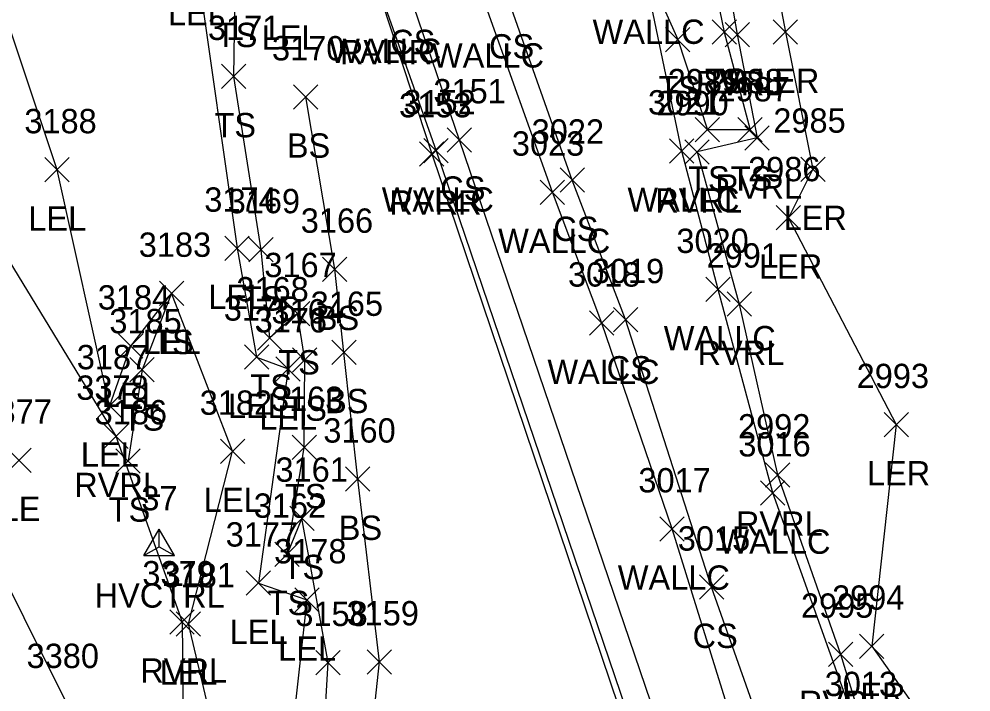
# Model space of a CAD drawing. Extents: x 1461855 to 1464118, y 556196 to 557441.
# Drawn here: x 1462111.2 to 1462189.5, y 556558.7 to 556614 of the extents above; entities that cross this region are included whole.
import ezdxf

# ---------------------------------------------------------------- set-up
doc = ezdxf.new("R2010")
doc.units = 0
for name, color, linetype in [('C_A', 7, 'Continuous'), ('C_I', 7, 'Continuous'), ('CPSM', 7, 'Continuous'), ('L_A', 7, 'Continuous'), ('L_I', 7, 'Continuous'), ('L_TIC', 7, 'Continuous'), ('LARO', 7, 'Continuous'), ('LAWE', 7, 'Continuous'), ('LELB', 7, 'Continuous'), ('LW', 7, 'Continuous')]:
    doc.layers.add(name, color=color, linetype=linetype)

msp = doc.modelspace()

# ---------------------------------------------------------------- linework, layer by layer
at = {"layer": 'CPSM'}
for p, q in [((1462121.477, 556569.921), (1462122.727, 556572.087)), ((1462123.977, 556569.921), (1462122.727, 556572.087)), ((1462122.727, 556570.643), (1462122.727, 556572.087)), ((1462121.477, 556569.921), (1462122.727, 556570.643)), ((1462122.727, 556570.643), (1462122.727, 556570.643)), ((1462122.727, 556570.643), (1462123.977, 556569.921)), ((1462121.477, 556569.921), (1462123.977, 556569.921))]:
    msp.add_line(p, q, dxfattribs=at)
at = {"layer": 'L_TIC'}
for points in [[(1462168.186, 556611.955), (1462170.186, 556613.955)], [(1462170.186, 556611.955), (1462168.186, 556613.955)], [(1462169.255, 556611.748), (1462171.255, 556613.748)], [(1462171.255, 556611.748), (1462169.255, 556613.748)], [(1462173.213, 556611.956), (1462175.213, 556613.956)], [(1462175.213, 556611.956), (1462173.213, 556613.956)], [(1462164.363, 556611.34), (1462166.363, 556613.34)], [(1462166.363, 556611.34), (1462164.363, 556613.34)], [(1462127.864, 556608.306), (1462129.864, 556610.306)], [(1462129.864, 556608.306), (1462127.864, 556610.306)], [(1462133.783, 556606.627), (1462135.783, 556608.627)], [(1462135.783, 556606.627), (1462133.783, 556608.627)], [(1462166.802, 556603.927), (1462168.802, 556605.927)], [(1462168.802, 556603.927), (1462166.802, 556605.927)], [(1462166.802, 556603.927), (1462168.802, 556605.927)], [(1462168.802, 556603.927), (1462166.802, 556605.927)], [(1462170.305, 556603.927), (1462172.305, 556605.927)], [(1462172.305, 556603.927), (1462170.305, 556605.927)], [(1462146.397, 556603.094), (1462148.397, 556605.094)], [(1462148.397, 556603.094), (1462146.397, 556605.094)], [(1462170.886, 556603.258), (1462172.886, 556605.258)], [(1462172.886, 556603.258), (1462170.886, 556605.258)], [(1462144.141, 556601.946), (1462146.141, 556603.946)], [(1462146.141, 556601.946), (1462144.141, 556603.946)], [(1462144.491, 556602.196), (1462146.491, 556604.196)], [(1462146.491, 556602.196), (1462144.491, 556604.196)], [(1462164.687, 556602.179), (1462166.687, 556604.179)], [(1462166.687, 556602.179), (1462164.687, 556604.179)], [(1462165.942, 556602.106), (1462167.942, 556604.106)], [(1462167.942, 556602.106), (1462165.942, 556604.106)], [(1462113.339, 556600.636), (1462115.339, 556602.636)], [(1462115.339, 556600.636), (1462113.339, 556602.636)], [(1462175.476, 556600.682), (1462177.476, 556602.682)], [(1462177.476, 556600.682), (1462175.476, 556602.682)], [(1462155.686, 556599.782), (1462157.686, 556601.782)], [(1462157.686, 556599.782), (1462155.686, 556601.782)], [(1462154.06, 556598.794), (1462156.06, 556600.794)], [(1462156.06, 556598.794), (1462154.06, 556600.794)], [(1462173.457, 556596.693), (1462175.457, 556598.693)], [(1462175.457, 556596.693), (1462173.457, 556598.693)], [(1462128.13, 556594.188), (1462130.13, 556596.188)], [(1462130.13, 556594.188), (1462128.13, 556596.188)], [(1462130.108, 556594.062), (1462132.108, 556596.062)], [(1462132.108, 556594.062), (1462130.108, 556596.062)], [(1462136.166, 556592.458), (1462138.166, 556594.458)], [(1462138.166, 556592.458), (1462136.166, 556594.458)], [(1462167.671, 556590.797), (1462169.671, 556592.797)], [(1462169.671, 556590.797), (1462167.671, 556592.797)], [(1462122.746, 556590.48), (1462124.746, 556592.48)], [(1462124.746, 556590.48), (1462122.746, 556592.48)], [(1462122.746, 556590.48), (1462124.746, 556592.48)], [(1462124.746, 556590.48), (1462122.746, 556592.48)], [(1462169.42, 556589.593), (1462171.42, 556591.593)], [(1462171.42, 556589.593), (1462169.42, 556591.593)], [(1462133.114, 556588.81), (1462135.114, 556590.81)], [(1462135.114, 556588.81), (1462133.114, 556590.81)], [(1462160.076, 556588.318), (1462162.076, 556590.318)], [(1462162.076, 556588.318), (1462160.076, 556590.318)], [(1462158.111, 556588.032), (1462160.111, 556590.032)], [(1462160.111, 556588.032), (1462158.111, 556590.032)], [(1462130.816, 556586.817), (1462132.816, 556588.817)], [(1462132.816, 556586.817), (1462130.816, 556588.817)], [(1462119.375, 556586.146), (1462121.375, 556588.146)], [(1462121.375, 556586.146), (1462119.375, 556588.146)], [(1462129.737, 556585.238), (1462131.737, 556587.238)], [(1462131.737, 556585.238), (1462129.737, 556587.238)], [(1462136.922, 556585.627), (1462138.922, 556587.627)], [(1462138.922, 556585.627), (1462136.922, 556587.627)], [(1462133.696, 556585.005), (1462135.696, 556587.005)], [(1462135.696, 556585.005), (1462133.696, 556587.005)], [(1462120.325, 556584.195), (1462122.325, 556586.195)], [(1462122.325, 556584.195), (1462120.325, 556586.195)], [(1462132.324, 556584.263), (1462134.324, 556586.263)], [(1462134.324, 556584.263), (1462132.324, 556586.263)], [(1462117.651, 556581.24), (1462119.651, 556583.24)], [(1462119.651, 556581.24), (1462117.651, 556583.24)], [(1462182.325, 556579.689), (1462184.325, 556581.689)], [(1462184.325, 556579.689), (1462182.325, 556581.689)], [(1462118.177, 556578.727), (1462120.177, 556580.727)], [(1462120.177, 556578.727), (1462118.177, 556580.727)], [(1462127.758, 556577.494), (1462129.758, 556579.494)], [(1462129.758, 556577.494), (1462127.758, 556579.494)], [(1462133.658, 556577.811), (1462135.658, 556579.811)], [(1462135.658, 556577.811), (1462133.658, 556579.811)], [(1462110.215, 556576.756), (1462112.215, 556578.756)], [(1462112.215, 556576.756), (1462110.215, 556578.756)], [(1462119.172, 556576.711), (1462121.172, 556578.711)], [(1462121.172, 556576.711), (1462119.172, 556578.711)], [(1462138.049, 556575.21), (1462140.049, 556577.21)], [(1462140.049, 556575.21), (1462138.049, 556577.21)], [(1462172.572, 556575.55), (1462174.572, 556577.55)], [(1462174.572, 556575.55), (1462172.572, 556577.55)], [(1462172.165, 556574.068), (1462174.165, 556576.068)], [(1462174.165, 556574.068), (1462172.165, 556576.068)], [(1462133.464, 556571.989), (1462135.464, 556573.989)], [(1462135.464, 556571.989), (1462133.464, 556573.989)], [(1462163.895, 556571.115), (1462165.895, 556573.115)], [(1462165.895, 556571.115), (1462163.895, 556573.115)], [(1462132.244, 556569.031), (1462134.244, 556571.031)], [(1462134.244, 556569.031), (1462132.244, 556571.031)], [(1462129.889, 556566.664), (1462131.889, 556568.664)], [(1462131.889, 556566.664), (1462129.889, 556568.664)], [(1462167.136, 556566.331), (1462169.136, 556568.331)], [(1462169.136, 556566.331), (1462167.136, 556568.331)], [(1462133.873, 556565.28), (1462135.873, 556567.28)], [(1462135.873, 556565.28), (1462133.873, 556567.28)], [(1462123.613, 556563.474), (1462125.613, 556565.474)], [(1462125.613, 556563.474), (1462123.613, 556565.474)], [(1462124.133, 556563.305), (1462126.133, 556565.305)], [(1462126.133, 556563.305), (1462124.133, 556565.305)], [(1462177.747, 556560.813), (1462179.747, 556562.813)], [(1462179.747, 556560.813), (1462177.747, 556562.813)], [(1462180.304, 556561.472), (1462182.304, 556563.472)], [(1462182.304, 556561.472), (1462180.304, 556563.472)], [(1462135.613, 556560.13), (1462137.613, 556562.13)], [(1462137.613, 556560.13), (1462135.613, 556562.13)], [(1462139.834, 556560.185), (1462141.834, 556562.185)], [(1462141.834, 556560.185), (1462139.834, 556562.185)]]:
    msp.add_lwpolyline(points, dxfattribs=at)
at = {"layer": 'LARO'}
for points in [[(1462153.543, 556698.226), (1462159.529, 556693.305), (1462162.233, 556679.751), (1462167.682, 556662.613), (1462169.082, 556643.16), (1462171.862, 556625.321), (1462174.213, 556612.956), (1462176.476, 556601.682), (1462174.457, 556597.693), (1462183.325, 556580.689), (1462181.304, 556562.472), (1462189.463, 556550.975), (1462182.605, 556534.635)], [(1462128.267, 556551.138), (1462125.133, 556564.305), (1462128.758, 556578.494), (1462123.746, 556591.48), (1462120.375, 556587.146), (1462118.651, 556582.24), (1462114.339, 556601.636), (1462108.703, 556618.463), (1462098.448, 556617.236), (1462094.693, 556608.84), (1462088.622, 556617.99), (1462090.264, 556635.589), (1462093.761, 556646.388), (1462094.044, 556655.088), (1462088.409, 556655.405), (1462085.382, 556651.508), (1462082.004, 556651.265), (1462078.128, 556651.639), (1462079.126, 556665.539), (1462072.726, 556676.797)], [(1462108.44, 556677.046), (1462114.001, 556662.205), (1462116.197, 556655.209), (1462120.026, 556641.487), (1462125.669, 556630.824), (1462129.521, 556622.314), (1462133.504, 556616.498), (1462125.817, 556618.515), (1462129.13, 556595.188), (1462130.737, 556586.238), (1462133.324, 556585.263), (1462130.889, 556567.664), (1462134.873, 556566.28), (1462133.035, 556549.7)]]:
    msp.add_lwpolyline(points, dxfattribs=at)
at = {"layer": 'LAWE'}
for points in [[(1462035.855, 556809.685), (1462040.285, 556805.29), (1462046.447, 556786.582), (1462047.954, 556769.867), (1462051.587, 556748.694), (1462051.929, 556721.581), (1462051.091, 556687.112), (1462052.825, 556666.076), (1462054.764, 556643.062), (1462061.562, 556623.629), (1462070.818, 556617.59), (1462084.777, 556608.704), (1462105.974, 556601.343), (1462119.177, 556579.727), (1462124.613, 556564.474), (1462124.915, 556535.352)], [(1462120.691, 556737.434), (1462122.423, 556720.718), (1462119.992, 556701.198), (1462119.681, 556688.809), (1462118.64, 556686.34), (1462114.371, 556676.303), (1462125.062, 556658.7), (1462126.988, 556641.518), (1462131.288, 556633.529), (1462137.745, 556624.648), (1462141.077, 556615.301), (1462145.141, 556602.946), (1462161.881, 556553.375), (1462138.756, 556543.397)], [(1462157.004, 556715.519), (1462153.543, 556698.226), (1462154.791, 556691.267), (1462159.421, 556679.928), (1462163.376, 556661.905), (1462166.279, 556641.444), (1462168.012, 556625.686), (1462170.255, 556612.748), (1462171.886, 556604.258), (1462166.942, 556603.106), (1462170.42, 556590.593), (1462173.572, 556576.55), (1462178.747, 556561.813), (1462182.208, 556550.438), (1462181.653, 556545.019), (1462176.294, 556542.787), (1462165.32, 556537.287)]]:
    msp.add_lwpolyline(points, dxfattribs=at)
at = {"layer": 'LELB'}
for points in [[(1462148.927, 556688.411), (1462148.332, 556679.235), (1462150.759, 556658.223), (1462154.021, 556642.891), (1462158.371, 556628.049), (1462165.363, 556612.34), (1462167.802, 556604.927)], [(1462046.194, 556686.747), (1462048.138, 556663.233), (1462044.201, 556642.081), (1462056.957, 556622.87), (1462067.983, 556610.68), (1462080.94, 556602.236), (1462101.79, 556592.319), (1462108.001, 556571.986), (1462115.176, 556557.681), (1462103.465, 556550.963), (1462124.915, 556535.352)], [(1462166.507, 556625.891), (1462169.186, 556612.955), (1462171.305, 556604.927), (1462167.802, 556604.927)], [(1462174.415, 556546.774), (1462173.201, 556552.992), (1462168.136, 556567.331), (1462161.076, 556589.318), (1462156.686, 556600.782), (1462151.404, 556615.782), (1462148.568, 556625.245)], [(1462140.968, 556623.1), (1462143.276, 556616.144), (1462147.397, 556604.094), (1462165.318, 556551.475)], [(1462135.623, 556544.315), (1462136.613, 556561.13), (1462134.464, 556572.989), (1462133.244, 556570.031), (1462134.658, 556578.811), (1462134.696, 556586.005), (1462134.114, 556589.81), (1462131.816, 556587.817), (1462131.108, 556595.062), (1462128.864, 556609.306), (1462128.979, 556616.721)], [(1462139.347, 556547.149), (1462140.834, 556561.185), (1462139.049, 556576.21), (1462137.922, 556586.627), (1462137.166, 556593.458), (1462134.783, 556607.627)], [(1462123.746, 556591.48), (1462121.325, 556585.195), (1462120.172, 556577.711)]]:
    msp.add_lwpolyline(points, dxfattribs=at)
at = {"layer": 'LW'}
for points in [[(1462143.044, 556630.161), (1462140.078, 556626.916), (1462137.923, 556624.597), (1462141.173, 556615.42), (1462145.491, 556603.196), (1462162.533, 556553.062)], [(1462165.028, 556537.928), (1462178.105, 556543.807), (1462180.56, 556544.806), (1462181.677, 556547.712), (1462181.204, 556550.448), (1462180.21, 556555.376), (1462173.165, 556575.068), (1462168.671, 556591.797), (1462165.687, 556603.179), (1462162.82, 556616.984), (1462158.792, 556624.78), (1462153.945, 556627.528), (1462148.568, 556625.245), (1462146.516, 556624.825), (1462140.968, 556623.1)], [(1462163.394, 556542.183), (1462174.415, 556546.774), (1462172.599, 556547.381), (1462164.895, 556572.115), (1462159.111, 556589.032), (1462155.06, 556599.794), (1462149.62, 556615.039), (1462146.516, 556624.825)]]:
    msp.add_lwpolyline(points, dxfattribs=at)

# ---------------------------------------------------------------- texts
at = {"layer": 'C_A'}
msp.add_text('HVCTRL', height=2, dxfattribs=at).set_placement((1462117.42, 556565.643))
at = {"layer": 'C_I'}
msp.add_text('37', height=2, dxfattribs=at).set_placement((1462121.263, 556573.643))
at = {"layer": 'L_A'}
for s, p in [('LEL', (1462123.455, 556613.515)), ('TS', (1462127.389, 556611.721)), ('WALLC', (1462158.355, 556611.984)), ('LEL', (1462131.142, 556611.498)), ('CS', (1462141.717, 556611.144)), ('WALLC', (1462136.708, 556610.42)), ('RVRR', (1462137.589, 556610.301)), ('CS', (1462149.845, 556610.782)), ('WALLC', (1462145.156, 556610.039)), ('TS', (1462167.595, 556607.955)), ('LER', (1462171.796, 556607.956)), ('TS', (1462163.773, 556607.34)), ('RVRL', (1462166.822, 556607.748)), ('TS', (1462127.273, 556604.306)), ('BS', (1462133.224, 556602.627)), ('TS', (1462166.211, 556599.927)), ('TS', (1462166.211, 556599.927)), ('TS', (1462169.715, 556599.927)), ('RVRL', (1462168.453, 556599.258)), ('CS', (1462145.838, 556599.094)), ('WALLC', (1462141.026, 556598.196)), ('RVRR', (1462141.653, 556597.946)), ('WALLC', (1462161.223, 556598.179)), ('RVRL', (1462163.508, 556598.106)), ('LEL', (1462111.977, 556596.636)), ('LER', (1462174.058, 556596.682)), ('CS', (1462155.127, 556595.782)), ('WALLC', (1462150.596, 556594.794)), ('LER', (1462172.039, 556592.693)), ('LEL', (1462126.768, 556590.188)), ('TS', (1462129.518, 556590.062)), ('BS', (1462135.607, 556588.458)), ('WALLC', (1462164.206, 556586.797)), ('LEL', (1462121.384, 556586.48)), ('TS', (1462122.155, 556586.48)), ('RVRL', (1462166.987, 556585.593)), ('TS', (1462132.524, 556584.81)), ('CS', (1462159.517, 556584.318)), ('WALLC', (1462154.646, 556584.032)), ('TS', (1462130.225, 556582.817)), ('LEL', (1462118.013, 556582.146)), ('LEL', (1462128.375, 556581.238)), ('BS', (1462136.363, 556581.627)), ('TS', (1462133.106, 556581.005)), ('TS', (1462119.734, 556580.195)), ('LEL', (1462130.962, 556580.263)), ('LEL', (1462116.289, 556577.24)), ('LER', (1462180.908, 556575.689)), ('RVRL', (1462115.744, 556574.727)), ('LEL', (1462126.396, 556573.494)), ('TS', (1462133.068, 556573.811)), ('LE', (1462109.703, 556572.756)), ('TS', (1462118.582, 556572.711)), ('BS', (1462137.49, 556571.21)), ('RVRL', (1462170.139, 556571.55)), ('WALLC', (1462168.701, 556570.068)), ('TS', (1462132.873, 556567.989)), ('WALLC', (1462160.43, 556567.115)), ('TS', (1462131.653, 556565.031)), ('LEL', (1462128.527, 556562.664)), ('CS', (1462166.577, 556562.331)), ('LEL', (1462132.51, 556561.28)), ('RVRL', (1462121.18, 556559.474)), ('LEL', (1462122.77, 556559.305)), ('LER', (1462178.886, 556557.472)), ('RVRL', (1462175.314, 556556.813))]:
    msp.add_text(s, height=2, dxfattribs=at).set_placement(p)
at = {"layer": 'L_I'}
for s, p in [('3171', (1462126.738, 556612.306)), ('3170', (1462132.003, 556610.627)), ('2989', (1462164.534, 556607.927)), ('2989', (1462164.534, 556607.927)), ('2988', (1462168.045, 556607.927)), ('3151', (1462145.271, 556607.094)), ('2987', (1462168.626, 556607.258)), ('3152', (1462142.798, 556606.196)), ('3021', (1462162.915, 556606.179)), ('3153', (1462142.448, 556605.946)), ('2990', (1462163.595, 556606.106)), ('3188', (1462111.646, 556604.636)), ('2985', (1462173.216, 556604.682)), ('3022', (1462153.348, 556603.782)), ('3023', (1462151.722, 556602.794)), ('2986', (1462171.142, 556600.693)), ('3174', (1462126.437, 556598.188)), ('3169', (1462128.36, 556598.062)), ('3166', (1462134.37, 556596.458)), ('3183', (1462121.053, 556594.48)), ('3183', (1462121.053, 556594.48)), ('3020', (1462165.246, 556594.797)), ('2991', (1462167.727, 556593.593)), ('3167', (1462131.374, 556592.81)), ('3019', (1462158.296, 556592.318)), ('3018', (1462156.339, 556592.032)), ('3168', (1462129.076, 556590.817)), ('3184', (1462117.682, 556590.146)), ('3175', (1462128.045, 556589.238)), ('3164', (1462131.956, 556589.005)), ('3165', (1462135.182, 556589.627)), ('3185', (1462118.632, 556588.195)), ('3176', (1462130.576, 556588.263)), ('3187', (1462115.958, 556585.24)), ('2993', (1462180.065, 556583.689)), ('3378', (1462115.917, 556582.727)), ('3182', (1462126.065, 556581.494)), ('3163', (1462131.918, 556581.811)), ('3377', (1462107.955, 556580.756)), ('3186', (1462117.424, 556580.711)), ('3160', (1462136.223, 556579.21)), ('2992', (1462170.312, 556579.55)), ('3016', (1462170.338, 556578.068)), ('3161', (1462132.29, 556575.989)), ('3017', (1462162.123, 556575.115)), ('3162', (1462130.504, 556573.031)), ('3177', (1462128.196, 556570.664)), ('3015', (1462165.364, 556570.331)), ('3178', (1462132.18, 556569.28)), ('3379', (1462121.346, 556567.474)), ('3181', (1462123.007, 556567.305)), ('2994', (1462178.044, 556565.472)), ('2995', (1462175.487, 556564.813)), ('3158', (1462133.92, 556564.13)), ('3159', (1462138.133, 556564.185)), ('3380', (1462111.83, 556560.681)), ('3013', (1462177.439, 556558.376))]:
    msp.add_text(s, height=2, dxfattribs=at).set_placement(p)

doc.saveas('drawing.dxf')
